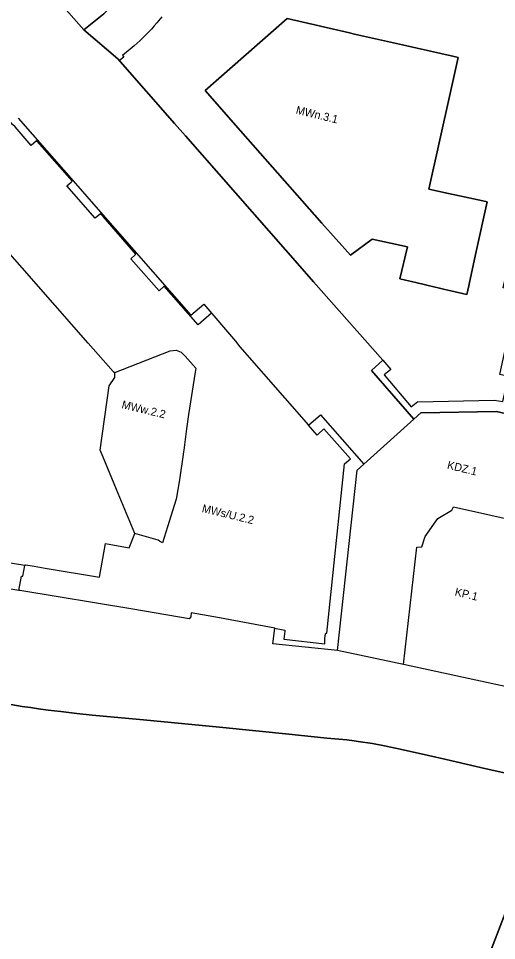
# Model space of a CAD drawing. Extents: x 7429686 to 7432896, y 5547954 to 5550600.
# Drawn here: x 7430853.5 to 7431092.2, y 5548709 to 5549169.6 of the extents above; entities that cross this region are included whole.
import ezdxf

# ---------------------------------------------------------------- set-up
doc = ezdxf.new("R2010")
doc.units = 0
for name, color, linetype in [('granica planu', 7, 'Continuous'), ('linie rozgraniczające', 7, 'Continuous'), ('obowiązująca linia zabudowy', 7, 'Continuous'), ('oznaczenia przeznaczeń', 7, 'Continuous')]:
    doc.layers.add(name, color=color, linetype=linetype)

msp = doc.modelspace()

# ---------------------------------------------------------------- linework, layer by layer
at = {"layer": 'granica planu'}
for points in [[(7431103.64, 5548791.04), (7431087.04, 5548794.84), (7431067.02, 5548799.37), (7431058.23, 5548801.37), (7431044.17, 5548804.52), (7431036.36, 5548806.23), (7431030.29, 5548807.37), (7431023.13, 5548808.5), (7431021.14, 5548808.74), (7431017.48, 5548809.19), (7431007.46, 5548810.17), (7430990.22, 5548811.9), (7430953.89, 5548815.54), (7430915.98, 5548819.29), (7430890.24, 5548821.56), (7430882.62, 5548822.49), (7430874.61, 5548823.34), (7430868.39, 5548824.05), (7430863.43, 5548824.74), (7430859.47, 5548825.35), (7430855.34, 5548825.98), (7430849.71, 5548826.87)], [(7431071.46, 5548657.37), (7431103.57, 5548740.91)]]:
    msp.add_lwpolyline(points, dxfattribs=at)
at = {"layer": 'linie rozgraniczające'}
for p, q in [((7430946.76, 5549133.52), (7430987.61, 5549169.48)), ((7430987.61, 5549169.48), (7430946.76, 5549133.52)), ((7430886.17, 5549163.92), (7430903.18, 5549149.46)), ((7431021.26, 5549161.75), (7431018.86, 5549162.35)), ((7431042.29, 5549157.02), (7431021.26, 5549161.75)), ((7431073.13, 5549150.09), (7431071.14, 5549150.53)), ((7431069.11, 5549132.09), (7431073.13, 5549150.09)), ((7430946.76, 5549133.52), (7430964.35, 5549113.53)), ((7431058.43, 5549084.35), (7431069.11, 5549132.09)), ((7430964.35, 5549113.53), (7431004.93, 5549067.41)), ((7431068.29, 5549082.1), (7431058.43, 5549084.35)), ((7431073.79, 5549080.95), (7431068.29, 5549082.1)), ((7431082.09, 5549053.21), (7431087.5, 5549077.97)), ((7431004.93, 5549067.41), (7431019.27, 5549051.36)), ((7431030.17, 5549059.41), (7431019.27, 5549051.36)), ((7431019.27, 5549051.36), (7431030.17, 5549059.41)), ((7431047.75, 5549055.55), (7431030.17, 5549059.41)), ((7431030.17, 5549059.41), (7431047.75, 5549055.55)), ((7431047.75, 5549055.55), (7431043.93, 5549039.53)), ((7431078.7, 5549037.71), (7431082.09, 5549053.21)), ((7431000.88, 5549038.08), (7431035.44, 5548998.87)), ((7431043.93, 5549039.53), (7431046.85, 5549038.85)), ((7431046.85, 5549038.85), (7431049.82, 5549038.15)), ((7431077.38, 5549031.69), (7431078.33, 5549036.03)), ((7431078.33, 5549036.03), (7431078.7, 5549037.71)), ((7431066.46, 5549034.24), (7431069.38, 5549033.56)), ((7431077.38, 5549031.69), (7431069.38, 5549033.56)), ((7431069.38, 5549033.56), (7431077.38, 5549031.69)), ((7431035.44, 5548998.87), (7431029.82, 5548993.79)), ((7431029.82, 5548993.79), (7431050.95, 5548969.47)), ((7431050.95, 5548969.47), (7431054.42, 5548972.62))]:
    msp.add_line(p, q, dxfattribs=at)
for points in [[(7430886.17, 5549163.92), (7430896.16, 5549171.92), (7430905.64, 5549181), (7430912.06, 5549189.23), (7430915.45, 5549194.85), (7430916.8, 5549198.49), (7430919.72, 5549206.79), (7430921.28, 5549211.46), (7430922.42, 5549216.2), (7430923.56, 5549220.95), (7430924.39, 5549225.55), (7430925.21, 5549230.15)], [(7430886.17, 5549163.92), (7430860.07, 5549193.67)], [(7430905.64, 5549181), (7430896.16, 5549171.92), (7430886.17, 5549163.92)], [(7430987.61, 5549169.48), (7431003.59, 5549165.9), (7431004.33, 5549165.72), (7431018.86, 5549162.35), (7431021.26, 5549161.75)], [(7431018.86, 5549162.35), (7431004.33, 5549165.72), (7431003.59, 5549165.9), (7430987.61, 5549169.48)], [(7431050.95, 5548969.47), (7431029.82, 5548993.79), (7431035.44, 5548998.87), (7431000.88, 5549038.08), (7430995.19, 5549044.59), (7430936.84, 5549110.97), (7430931.4, 5549117.17), (7430903.18, 5549149.46), (7430886.17, 5549163.92)], [(7431021.26, 5549161.75), (7431042.29, 5549157.02), (7431045.22, 5549156.42), (7431052.6, 5549154.69), (7431071.14, 5549150.53), (7431073.13, 5549150.09)], [(7431071.14, 5549150.53), (7431052.6, 5549154.69), (7431045.22, 5549156.42), (7431042.29, 5549157.02)], [(7430903.18, 5549149.46), (7430931.4, 5549117.17), (7430936.84, 5549110.97)], [(7431073.13, 5549150.09), (7431069.11, 5549132.09), (7431058.43, 5549084.35)], [(7431019.27, 5549051.36), (7431004.93, 5549067.41), (7430964.35, 5549113.53), (7430946.76, 5549133.52)], [(7430853.3, 5549119.81), (7430883.07, 5549085.86)], [(7430936.84, 5549110.97), (7430995.19, 5549044.59), (7431000.88, 5549038.08)], [(7430883.07, 5549085.86), (7430892.15, 5549075.5)], [(7431058.43, 5549084.35), (7431068.29, 5549082.1), (7431073.79, 5549080.95), (7431085.31, 5549078.44), (7431087.5, 5549077.97)], [(7431087.5, 5549077.97), (7431085.31, 5549078.44), (7431073.79, 5549080.95)], [(7431087.5, 5549077.97), (7431082.09, 5549053.21), (7431078.7, 5549037.71)], [(7430892.15, 5549075.5), (7430939.62, 5549021.36)], [(7430855.29, 5549044.96), (7430835.74, 5549067.17)], [(7431069.38, 5549033.56), (7431066.46, 5549034.24), (7431063.69, 5549034.9), (7431060.92, 5549035.55), (7431058.15, 5549036.19), (7431055.37, 5549036.85), (7431052.6, 5549037.5), (7431049.82, 5549038.15), (7431046.85, 5549038.85), (7431043.93, 5549039.53), (7431047.75, 5549055.55)], [(7430888.22, 5549007.36), (7430855.29, 5549044.96)], [(7431049.82, 5549038.15), (7431052.6, 5549037.5), (7431055.37, 5549036.85), (7431058.15, 5549036.19)], [(7431058.15, 5549036.19), (7431060.92, 5549035.55), (7431063.69, 5549034.9), (7431066.46, 5549034.24)], [(7431078.7, 5549037.71), (7431078.33, 5549036.03), (7431077.38, 5549031.69)], [(7430939.62, 5549021.36), (7430946, 5549026.8)], [(7430946, 5549026.8), (7430961.94, 5549008.37)], [(7430961.94, 5549008.37), (7430964.07, 5549005.56)], [(7430900.77, 5548993.24), (7430888.22, 5549007.36)], [(7430901.63, 5548992.76), (7430929.28, 5549003.48)], [(7430929.28, 5549003.48), (7430932.25, 5549003.82)], [(7430932.25, 5549003.82), (7430934.71, 5549002.86)], [(7430964.07, 5549005.56), (7430998.32, 5548966.51)], [(7430934.71, 5549002.86), (7430936.71, 5549000.9)], [(7430936.71, 5549000.9), (7430942.03, 5548994.92)], [(7430942.03, 5548994.92), (7430941.73, 5548992.95)], [(7430898.73, 5548986.05), (7430901.64, 5548990.26)], [(7430901.25, 5548992.82), (7430900.77, 5548993.24)], [(7430901.63, 5548992.76), (7430901.25, 5548992.82)], [(7430901.64, 5548990.26), (7430901.63, 5548992.76)], [(7430941.73, 5548992.95), (7430938.47, 5548971.81)], [(7430894.36, 5548953.97), (7430898.73, 5548986.05)], [(7430938.47, 5548971.81), (7430937.37, 5548964.62)], [(7430998.32, 5548966.51), (7431004.28, 5548971.66)], [(7431004.28, 5548971.66), (7431025.96, 5548946.98)], [(7431099.36, 5548971.58), (7431092.19, 5548973.2), (7431054.42, 5548972.62), (7431050.95, 5548969.47)], [(7431054.42, 5548972.62), (7431092.19, 5548973.2), (7431099.36, 5548971.58)], [(7431025.96, 5548946.98), (7431050.95, 5548969.47)], [(7430937.37, 5548964.62), (7430936.03, 5548953.98)], [(7430895.79, 5548950.39), (7430894.36, 5548953.97)], [(7430935.88, 5548953.32), (7430935.76, 5548951.74)], [(7430936.03, 5548953.98), (7430935.88, 5548953.32)], [(7430902.49, 5548934.31), (7430895.79, 5548950.39)], [(7430935.76, 5548951.74), (7430933.85, 5548939.2)], [(7431012.8, 5548853.95), (7431022.56, 5548943.9)], [(7431022.56, 5548943.9), (7431025.96, 5548946.98)], [(7430933.85, 5548939.2), (7430932.23, 5548929.4)], [(7430911.67, 5548912.3), (7430902.49, 5548934.31)], [(7430932.23, 5548929.4), (7430927.97, 5548915.7)], [(7431069.85, 5548923.99), (7431070.7, 5548925.58)], [(7431070.7, 5548925.58), (7431125.23, 5548913.5)], [(7431062.93, 5548919.82), (7431069.85, 5548923.99)], [(7430927.97, 5548915.7), (7430925.48, 5548907.69)], [(7431056.67, 5548910.8), (7431062.17, 5548918.73)], [(7431062.17, 5548918.73), (7431062.93, 5548919.82)], [(7430856.6, 5548896.26), (7430752.48, 5548913.2)], [(7430908.81, 5548905.15), (7430911.67, 5548912.3)], [(7430923.21, 5548909.04), (7430911.67, 5548912.3)], [(7430894.04, 5548890.54), (7430896.93, 5548907.28)], [(7430896.93, 5548907.28), (7430908.81, 5548905.15)], [(7430923.94, 5548908.55), (7430923.21, 5548909.04)], [(7430925.48, 5548907.69), (7430923.94, 5548908.55)], [(7431054.9, 5548905.67), (7431056.67, 5548910.8)], [(7431045.7, 5548846.88), (7431052.45, 5548905.55)], [(7431052.45, 5548905.55), (7431054.9, 5548905.67)], [(7430853.67, 5548883.88), (7430750.63, 5548900.65)], [(7430855.68, 5548891.03), (7430856.6, 5548896.26)], [(7430856.6, 5548896.26), (7430857.18, 5548896.67)], [(7430857.18, 5548896.67), (7430861.27, 5548896)], [(7430861.27, 5548896), (7430866.86, 5548895)], [(7430866.86, 5548895), (7430894.04, 5548890.54)], [(7430853.67, 5548883.88), (7430855, 5548891.09)], [(7430855, 5548891.09), (7430855.68, 5548891.03)], [(7430854.16, 5548883.8), (7430853.67, 5548883.88)], [(7430910.57, 5548874.59), (7430854.16, 5548883.8)], [(7430938.66, 5548869.7), (7430910.57, 5548874.59)], [(7430939.61, 5548870.69), (7430938.66, 5548869.7)], [(7430939.82, 5548872.78), (7430939.61, 5548870.69)], [(7430953.86, 5548870.14), (7430939.82, 5548872.78)], [(7430981.46, 5548865.01), (7430953.86, 5548870.14)], [(7430980.46, 5548857.18), (7430981.46, 5548865.01)], [(7431012.8, 5548853.95), (7430980.46, 5548857.18)], [(7431045.7, 5548846.88), (7431012.8, 5548853.95)], [(7431114.24, 5548832.14), (7431045.7, 5548846.88)], [(7430849.71, 5548826.87), (7430855.34, 5548825.98), (7430859.47, 5548825.35), (7430863.43, 5548824.74), (7430868.39, 5548824.05), (7430874.61, 5548823.34), (7430882.62, 5548822.49), (7430890.24, 5548821.56), (7430915.98, 5548819.29), (7430953.89, 5548815.54), (7430990.22, 5548811.9), (7431007.46, 5548810.17), (7431017.48, 5548809.19), (7431021.14, 5548808.74), (7431023.13, 5548808.5), (7431030.29, 5548807.37), (7431036.36, 5548806.23), (7431044.17, 5548804.52), (7431058.23, 5548801.37), (7431067.02, 5548799.37), (7431087.04, 5548794.84), (7431103.64, 5548791.04)], [(7431096.99, 5548723.79), (7431071.46, 5548657.37), (7431073.95, 5548655.85), (7431087.73, 5548647.48), (7431090.74, 5548646.26), (7431120.62, 5548634.28), (7431121.74, 5548633.66), (7431139.89, 5548623.62), (7431141.79, 5548622.57), (7431167.76, 5548605.34), (7431168.74, 5548604.6), (7431185.78, 5548591.8), (7431187.8, 5548590.29), (7431211.94, 5548568.47), (7431213, 5548567.41), (7431226.69, 5548553.76), (7431229.12, 5548551.33), (7431244.4, 5548517.92), (7431276.39, 5548531.74)]]:
    msp.add_lwpolyline(points, dxfattribs=at)
at = {"layer": 'obowiązująca linia zabudowy'}
for p, q in [((7430943.21, 5549016.62), (7430926.24, 5549035.82)), ((7430949.81, 5549022.4), (7430943.21, 5549016.62))]:
    msp.add_line(p, q, dxfattribs=at)
for points in [[(7430925.14, 5549170.44), (7430922.6, 5549167.33), (7430921.32, 5549165.86), (7430919.93, 5549164.28), (7430917.18, 5549161.41), (7430914.31, 5549158.6), (7430911.31, 5549155.96), (7430905.38, 5549151.13), (7430906.03, 5549150.3), (7430903.95, 5549148.57)], [(7430862.57, 5549108.47), (7430859.9, 5549106.15), (7430851.84, 5549115.38), (7430850.54, 5549116.62), (7430839.58, 5549129.18)], [(7430880.27, 5549088.33), (7430863.99, 5549106.86), (7430862.57, 5549108.47)], [(7430894.49, 5549072.07), (7430891.75, 5549069.9), (7430877.62, 5549085.93), (7430879.76, 5549087.87), (7430880.27, 5549088.33)], [(7430912.16, 5549051.77), (7430895.74, 5549070.63), (7430894.49, 5549072.07)], [(7430926.24, 5549035.82), (7430923.71, 5549033.6), (7430909.63, 5549049.5), (7430911.84, 5549051.48), (7430912.16, 5549051.77)], [(7431035.44, 5548998.87), (7431039.37, 5548994.23), (7431036.15, 5548991.51), (7431049.63, 5548975.58), (7431052.85, 5548978.31), (7431053, 5548978.14), (7431091.06, 5548978.99), (7431095.4, 5548978.21), (7431098.15, 5548990.74), (7431093.85, 5548991.69), (7431100.27, 5549020.87), (7431104.88, 5549019.94), (7431107.42, 5549032.19), (7431103.47, 5549033.22), (7431103.02, 5549033.38), (7431095.59, 5549035), (7431096.75, 5549040.14), (7431098.96, 5549039.76)], [(7430981.42, 5548864.99), (7430986.52, 5548864.04), (7430986.49, 5548863.56), (7430986.48, 5548863.53), (7430986, 5548859.48), (7431006.46, 5548857.26), (7431006.57, 5548859.59), (7431006.65, 5548861.37), (7431006.92, 5548862.56), (7431007.52, 5548862.54), (7431016.28, 5548947.06), (7431019.24, 5548949.69), (7431006.03, 5548964.55), (7431002.97, 5548961.82), (7431002.63, 5548961.52), (7430998.32, 5548966.51)]]:
    msp.add_lwpolyline(points, dxfattribs=at)

# ---------------------------------------------------------------- texts
at = {"layer": 'oznaczenia przeznaczeń'}
for s, p in [('MWn.3.1', (7430991.76, 5549122.1)), ('MWw.2.2', (7430904.76, 5548974.99)), ('KDZ.1', (7431067.29, 5548944.78)), ('MWs/U.2.2', (7430944.85, 5548923.1)), ('KP.1', (7431071.12, 5548881.44))]:
    msp.add_text(s, height=4, rotation=346.4891, dxfattribs=at).set_placement(p)

doc.saveas('drawing.dxf')
